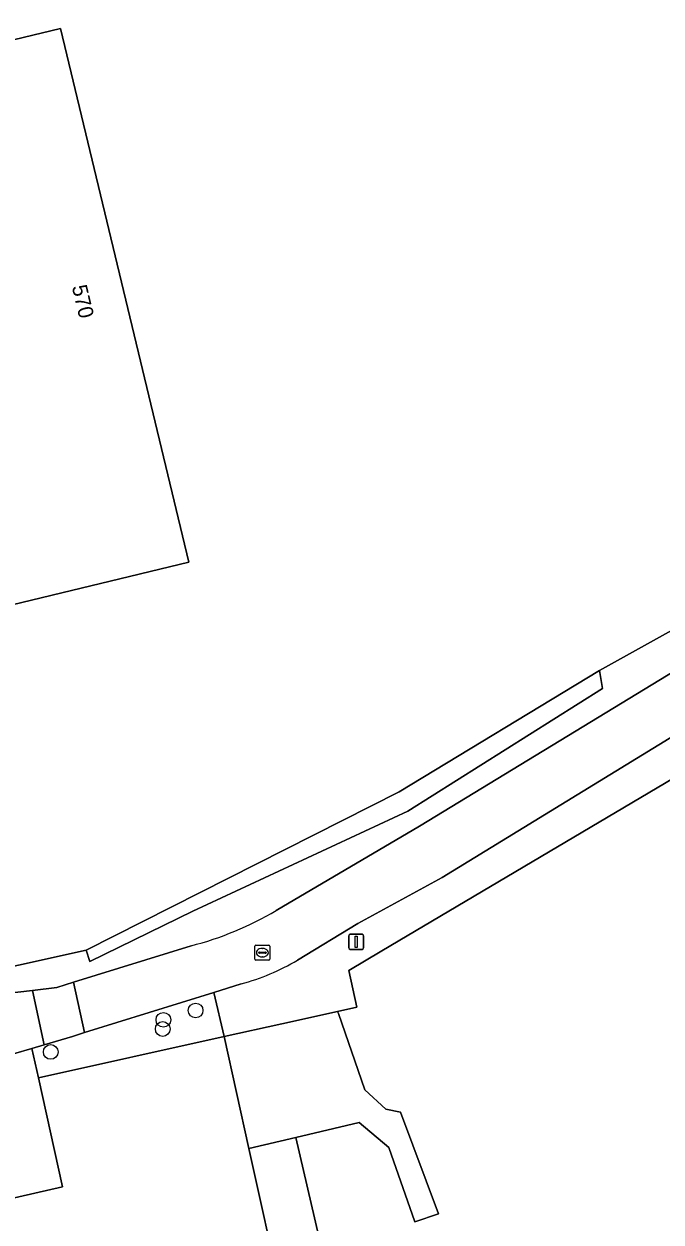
# Model space of a CAD drawing. Extents: x 164494 to 166241, y 382475 to 384495.
# Drawn here: x 164719.3 to 164761.6, y 383443.9 to 383523.4 of the extents above; entities that cross this region are included whole.
import ezdxf

# ---------------------------------------------------------------- set-up
doc = ezdxf.new("R2010")
doc.units = 0
for name, color, linetype in [('IMGEO_Boom', 7, 'Continuous'), ('IMGEO_Erf', 7, 'Continuous'), ('IMGEO_Grasland_overig', 7, 'Continuous'), ('IMGEO_Groenvoorziening', 7, 'Continuous'), ('IMGEO_Hek', 7, 'Continuous'), ('IMGEO_Lichtmast', 7, 'Continuous'), ('IMGEO_Pand', 7, 'Continuous'), ('IMGEO_Pand_nummerreeks', 7, 'Continuous'), ('IMGEO_Rijbaan_lokaal_open', 7, 'Continuous'), ('IMGEO_Rioolput', 7, 'Continuous'), ('IMGEO_Voetpad_open', 7, 'Continuous'), ('IMGEO_Waterloop', 7, 'Continuous')]:
    doc.layers.add(name, color=color, linetype=linetype)

msp = doc.modelspace()

# ---------------------------------------------------------------- linework, layer by layer
at = {"layer": 'IMGEO_Boom'}
for centre in [(164730.724, 383457.909), (164728.584, 383457.288), (164728.54, 383456.679), (164721.106, 383455.158)]:
    msp.add_circle(centre, 0.489, dxfattribs=at)
at = {"layer": 'IMGEO_Erf'}
for points in [[(164662.344, 383448.801), (164663.225, 383448.827), (164664.07, 383448.843), (164665.63, 383449.11), (164723.453, 383461.907), (164744.242, 383472.417), (164757.54, 383480.473), (164762.712, 383483.342), (164781.141, 383494.371), (164788.505, 383499.077), (164795.364, 383502.697), (164807.992, 383510.616), (164802.122, 383533.207)], [(164713.732, 383444.341), (164721.882, 383446.198), (164720.284, 383453.449), (164719.856, 383455.391), (164718.625, 383455.027)]]:
    msp.add_lwpolyline(points, dxfattribs=at)
msp.add_lwpolyline([(164730.267, 383487.654), (164656.027, 383469.749), (164647.473, 383505.183), (164721.758, 383523.074)], close=True, dxfattribs=at)
at = {"layer": 'IMGEO_Grasland_overig'}
msp.add_lwpolyline([(164737.368, 383449.485), (164734.264, 383448.756), (164736.451, 383438.887), (164739.046, 383427.179), (164738.851, 383427.135), (164739.244, 383425.389), (164739.434, 383425.431), (164741.194, 383417.588), (164744.613, 383402.354), (164747.346, 383390.178), (164750.963, 383391.02)], close=True, dxfattribs=at)
at = {"layer": 'IMGEO_Groenvoorziening'}
for points in [[(164790.471, 383497.065), (164794.753, 383499.407), (164796.221, 383500), (164808.828, 383505.036), (164808.959, 383506.852), (164796.236, 383501.305), (164795.697, 383502.499), (164795.364, 383502.697), (164788.505, 383499.077), (164781.141, 383494.371), (164762.712, 383483.342), (164757.54, 383480.473), (164757.747, 383479.263), (164744.81, 383471.136), (164730.536, 383464.501), (164723.693, 383461.162), (164723.453, 383461.907), (164665.63, 383449.11), (164664.07, 383448.843), (164663.225, 383448.827), (164662.344, 383448.801)], [(164736.073, 383464.54), (164745.588, 383470.135), (164770.361, 383485.201), (164790.471, 383497.065)], [(164814.936, 383417.889), (164783.794, 383461.004), (164781.789, 383463.825), (164771.873, 383478.714), (164771.699, 383478.975), (164771.151, 383478.63), (164772.583, 383475.997), (164765.09, 383471.534), (164763.63, 383474.017), (164763.042, 383473.669), (164743.085, 383461.862), (164740.895, 383460.566), (164741.434, 383458.132), (164740.154, 383457.849), (164740.206, 383457.698), (164741.949, 383452.648), (164743.354, 383451.363), (164744.321, 383451.166), (164746.846, 383444.411), (164745.27, 383443.883), (164743.549, 383448.824), (164741.582, 383450.474), (164737.368, 383449.485), (164750.963, 383391.02)], [(164665.421, 383446.666), (164678.342, 383449.582), (164693.004, 383452.936), (164708.916, 383456.753), (164712.427, 383457.585), (164717.739, 383458.983), (164719.895, 383459.238), (164721.503, 383459.428), (164722.622, 383459.776), (164730.422, 383462.201)]]:
    msp.add_lwpolyline(points, dxfattribs=at)
msp.add_lwpolyline([(164731.926, 383459.105), (164723.35, 383456.437), (164722.557, 383456.19), (164720.68, 383455.635), (164719.856, 383455.391), (164720.284, 383453.449), (164732.618, 383456.18)], close=True, dxfattribs=at)
msp.add_arc((164724.919, 383483.492), 21.991, 284.49179, 300.47843, dxfattribs=at)
at = {"layer": 'IMGEO_Hek'}
msp.add_lwpolyline([(164771.699, 383478.975), (164771.151, 383478.63), (164772.583, 383475.997), (164765.09, 383471.534), (164763.63, 383474.017), (164763.042, 383473.669), (164743.085, 383461.862), (164740.895, 383460.566), (164741.434, 383458.132), (164740.154, 383457.849)], dxfattribs=at)
at = {"layer": 'IMGEO_Lichtmast'}
for p, q in [((164740.892, 383462.063), (164740.892, 383462.863)), ((164740.892, 383462.863), (164740.892, 383462.063)), ((164740.992, 383462.963), (164741.782, 383462.963)), ((164741.782, 383462.963), (164740.992, 383462.963)), ((164741.882, 383462.863), (164741.882, 383462.063)), ((164741.882, 383462.063), (164741.882, 383462.863)), ((164741.782, 383461.963), (164740.992, 383461.963)), ((164740.992, 383461.963), (164741.782, 383461.963))]:
    msp.add_line(p, q, dxfattribs=at)
msp.add_lwpolyline([(164741.312, 383462.838), (164741.462, 383462.838), (164741.462, 383462.088), (164741.312, 383462.088), (164741.312, 383462.838)], dxfattribs=at)
for centre, start, end in [((164740.992, 383462.863), 90, 180), ((164740.992, 383462.863), 90, 180), ((164741.782, 383462.863), 0, 90), ((164741.782, 383462.863), 360, 90), ((164740.992, 383462.063), 180, 270), ((164740.992, 383462.063), 180, 270), ((164741.782, 383462.063), 270, 0), ((164741.782, 383462.063), 270, 0)]:
    msp.add_arc(centre, 0.1, start, end, dxfattribs=at)
at = {"layer": 'IMGEO_Pand'}
for points in [[(164656.027, 383469.749), (164730.267, 383487.654), (164721.758, 383523.074), (164647.473, 383505.183)], [(164734.264, 383448.756), (164732.618, 383456.18), (164720.284, 383453.449), (164721.882, 383446.198), (164713.732, 383444.341), (164715.87, 383434.212), (164719.515, 383435.099), (164719.645, 383434.565), (164721.137, 383434.904), (164721.007, 383435.439), (164731.927, 383437.925), (164736.451, 383438.887)]]:
    msp.add_lwpolyline(points, close=True, dxfattribs=at)
at = {"layer": 'IMGEO_Rijbaan_lokaal_open'}
for points in [[(164808.828, 383505.036), (164796.221, 383500), (164794.753, 383499.407), (164790.471, 383497.065), (164770.361, 383485.201), (164745.588, 383470.135), (164736.073, 383464.54)], [(164737.479, 383461.248), (164741.488, 383463.681), (164747.101, 383466.722), (164771.534, 383481.679), (164771.708, 383481.781), (164792.485, 383494.012), (164796.587, 383496.145), (164806.227, 383500), (164810.262, 383501.572)], [(164730.422, 383462.201), (164722.622, 383459.776), (164723.35, 383456.437), (164731.926, 383459.105), (164733.751, 383459.673)], [(164666.487, 383442.83), (164696.172, 383449.592), (164718.625, 383455.027), (164719.856, 383455.391), (164720.68, 383455.635), (164719.895, 383459.238), (164717.739, 383458.983), (164712.427, 383457.585), (164708.916, 383456.753), (164693.004, 383452.936), (164678.342, 383449.582), (164665.421, 383446.666)]]:
    msp.add_lwpolyline(points, dxfattribs=at)
msp.add_lwpolyline([(164722.622, 383459.776), (164721.503, 383459.428), (164719.895, 383459.238), (164720.68, 383455.635), (164722.557, 383456.19), (164723.35, 383456.437)], close=True, dxfattribs=at)
for centre, radius, start, end in [((164724.919, 383483.492), 21.991, 284.49179, 300.47843), ((164729.888, 383474.017), 14.855, 285.07406, 300.73197)]:
    msp.add_arc(centre, radius, start, end, dxfattribs=at)
at = {"layer": 'IMGEO_Rioolput'}
for p, q in [((164734.657, 383461.319), (164734.657, 383462.171)), ((164734.732, 383462.245), (164735.584, 383462.245)), ((164735.658, 383462.171), (164735.658, 383461.319)), ((164734.916, 383461.739), (164734.916, 383461.751)), ((164735.354, 383461.702), (164734.956, 383461.702)), ((164734.959, 383461.788), (164735.357, 383461.788)), ((164735.168, 383461.465), (164735.143, 383461.465)), ((164735.145, 383462.025), (164735.17, 383462.025)), ((164735.4, 383461.751), (164735.4, 383461.739)), ((164735.584, 383461.245), (164734.732, 383461.245))]:
    msp.add_line(p, q, dxfattribs=at)
for points in [[(164734.657, 383461.319), (164734.657, 383462.171)], [(164734.732, 383462.245), (164735.584, 383462.245)], [(164735.658, 383462.171), (164735.658, 383461.319)], [(164735.584, 383461.245), (164734.732, 383461.245)]]:
    msp.add_lwpolyline(points, dxfattribs=at)
for centre, radius, start, end in [((164734.734, 383462.169), 0.0765, 91.55205, 178.44795), ((164734.734, 383462.169), 0.0765, 91.55205, 178.44795), ((164735.582, 383462.169), 0.0765, 1.55205, 88.44795), ((164735.582, 383462.169), 0.0765, 1.55205, 88.44795), ((164734.734, 383461.321), 0.0765, 181.55205, 268.44795), ((164734.734, 383461.321), 0.0765, 181.55205, 268.44795), ((164734.956, 383461.748), 0.0403, 85.87752, 175.75265), ((164734.953, 383461.738), 0.0366, 178.93798, 274.71019), ((164735.357, 383461.745), 0.043, 264.86636, 352.45326), ((164735.361, 383461.75), 0.0386, 1.73085, 96.63898), ((164735.582, 383461.321), 0.0765, 271.55205, 358.44795), ((164735.582, 383461.321), 0.0765, 271.55205, 358.44795)]:
    msp.add_arc(centre, radius, start, end, dxfattribs=at)
for centre, major_axis, ratio, start_param, end_param in [((164735.144, 383461.745), (-0.387, 0.002), 0.722429, 4.712389, 7.853982), ((164735.169, 383461.745), (-0.39, 0.002), 0.717154, 1.570796, 4.712389)]:
    msp.add_ellipse(centre, major_axis=major_axis, ratio=ratio, start_param=start_param, end_param=end_param, dxfattribs=at)
at = {"layer": 'IMGEO_Voetpad_open'}
for points in [[(164740.895, 383460.566), (164743.085, 383461.862), (164763.042, 383473.669), (164763.63, 383474.017), (164765.09, 383471.534), (164772.583, 383475.997), (164771.151, 383478.63), (164771.699, 383478.975), (164770.982, 383480.051), (164772.275, 383480.798), (164771.708, 383481.781), (164771.534, 383481.679), (164747.101, 383466.722), (164741.488, 383463.681), (164737.479, 383461.248)], [(164733.751, 383459.673), (164731.926, 383459.105), (164732.618, 383456.18), (164736.455, 383457.03), (164740.154, 383457.849), (164741.434, 383458.132), (164740.895, 383460.566)]]:
    msp.add_lwpolyline(points, dxfattribs=at)
msp.add_lwpolyline([(164744.321, 383451.166), (164743.354, 383451.363), (164741.949, 383452.648), (164740.206, 383457.698), (164740.154, 383457.849), (164736.455, 383457.03), (164732.618, 383456.18), (164734.264, 383448.756), (164737.368, 383449.485), (164741.582, 383450.474), (164743.549, 383448.824), (164745.27, 383443.883), (164746.846, 383444.411)], close=True, dxfattribs=at)
msp.add_arc((164729.888, 383474.017), 14.855, 285.07406, 300.73197, dxfattribs=at)
at = {"layer": 'IMGEO_Waterloop'}
msp.add_lwpolyline([(164723.453, 383461.907), (164723.693, 383461.162), (164730.536, 383464.501), (164744.81, 383471.136), (164757.747, 383479.263), (164757.54, 383480.473), (164744.242, 383472.417)], close=True, dxfattribs=at)

# ---------------------------------------------------------------- texts
at = {"layer": 'IMGEO_Pand_nummerreeks'}
msp.add_text('570', height=1, rotation=283.50827, dxfattribs=at).set_placement((164722.503, 383505.932))

doc.saveas('drawing.dxf')
